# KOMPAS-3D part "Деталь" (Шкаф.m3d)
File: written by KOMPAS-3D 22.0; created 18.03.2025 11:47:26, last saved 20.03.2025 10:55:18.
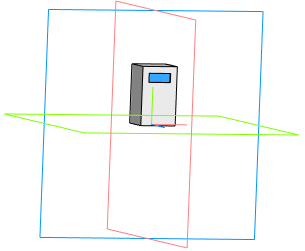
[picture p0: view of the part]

Document properties: Автор: Пользователь Windows; Полное имя файла: C:\Users\Student\Documents\Картошечка\База Сабнатика\Мебель\Шкаф.m3d

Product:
- Part/product: Деталь
    Масса: 0.005696

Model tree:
1. Эскиз:1
2. Элемент выдавливания:1
     Расстояние 1 = 7
3. Эскиз:3  (with: Элемент выдавливания:1)
4. Элемент выдавливания:3
     Расстояние 2 = 0.3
